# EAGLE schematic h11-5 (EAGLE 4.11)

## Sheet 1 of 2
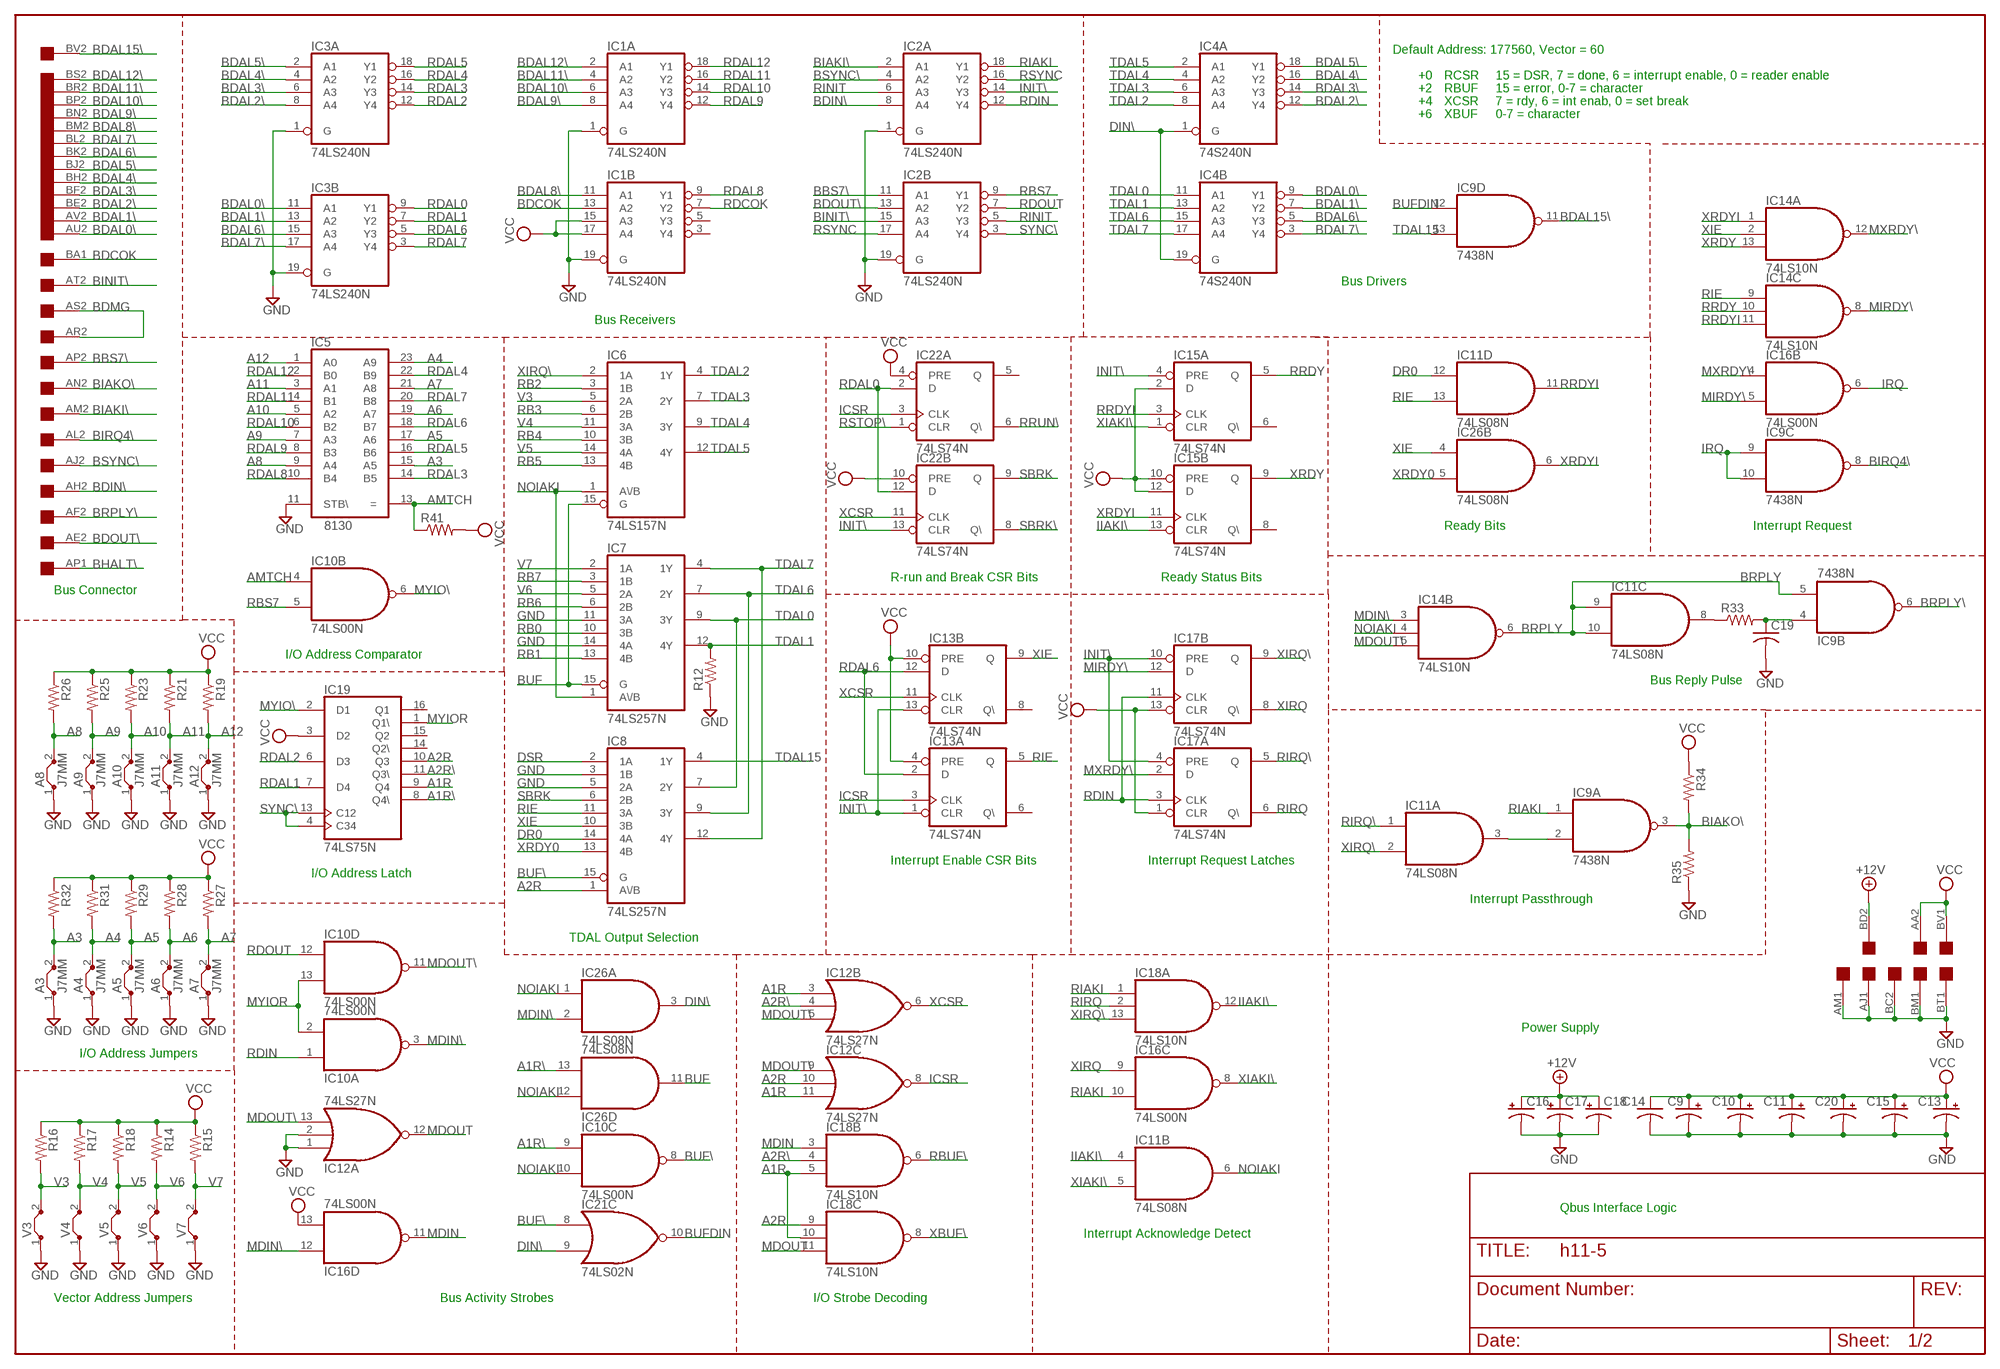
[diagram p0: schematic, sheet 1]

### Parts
A3  J7MM  [07]
A4  J7MM  [07]
A5  J7MM  [07]
A6  J7MM  [07]
A7  J7MM  [07]
A8  J7MM  [07]
A9  J7MM  [07]
A10  J7MM  [07]
A11  J7MM  [07]
A12  J7MM  [07]
C9  CPOL-USB45181B  [B45181B]
C10  CPOL-USB45181B  [B45181B]
C11  CPOL-USB45181B  [B45181B]
C13  CPOL-USB45181B  [B45181B]
C14  C-US075-032X103  [C075-032X103]
C15  CPOL-USB45181B  [B45181B]
C16  CPOL-USB45181B  [B45181B]
C17  CPOL-USB45181B  [B45181B]
C18  CPOL-USB45181B  [B45181B]
C19  C-US075-032X103  [C075-032X103]
C20  CPOL-USB45181B  [B45181B]
EDGE$  DOUBLE  [EDGE-CON4]
IC1  74LS240N  [DIL20]
IC2  74LS240N  [DIL20]
IC3  74LS240N  [DIL20]
IC4  74S240N  [DIL20]
IC5  8130  [DIL24]
IC6  74LS157N  [DIL16]
IC7  74LS257N  [DIL16]
IC8  74LS257N  [DIL16]
IC9  7438N  74LS38N  [DIL14]
IC10  74LS00N  [DIL14]
IC11  74LS08N  [DIL14]
IC12  74LS27N  [DIL14]
IC13  74LS74N  [DIL14]
IC14  74LS10N  [DIL14]
IC15  74LS74N  [DIL14]
IC16  74LS00N  [DIL14]
IC17  74LS74N  [DIL14]
IC18  74LS10N  [DIL14]
IC19  74LS75N  [DIL16]
IC21  74LS02N  [DIL14]
IC22  74LS74N  [DIL14]
IC26  74LS08N  [DIL14]
R12  R-US_0207/10  [0207/10]
R14  R-US_0207/10  [0207/10]
R15  R-US_0207/10  [0207/10]
R16  R-US_0207/10  [0207/10]
R17  R-US_0207/10  [0207/10]
R18  R-US_0207/10  [0207/10]
R19  R-US_0207/10  [0207/10]
R21  R-US_0207/10  [0207/10]
R23  R-US_0207/10  [0207/10]
R25  R-US_0207/10  [0207/10]
R26  R-US_0207/10  [0207/10]
R27  R-US_0207/10  [0207/10]
R28  R-US_0207/10  [0207/10]
R29  R-US_0207/10  [0207/10]
R31  R-US_0207/10  [0207/10]
R32  R-US_0207/10  [0207/10]
R33  R-US_0207/10  [0207/10]
R34  R-US_0207/10  [0207/10]
R35  R-US_0207/10  [0207/10]
R41  R-US_0207/10  [0207/10]
V3  J7MM  [07]
V4  J7MM  [07]
V5  J7MM  [07]
V6  J7MM  [07]
V7  J7MM  [07]

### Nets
+12V [Supply]: C16.+ C17.+ C18.+ EDGE$.BD2 ; also sheet 2
A1R: IC12.3(B:I0) IC12.11(C:I2) IC18.5(B:I2) IC18.10(C:I1) IC19.9(Q4)
A1R\: IC10.9(C:I0) IC19.8(Q4\) IC26.13(D:I1)
A2R: IC8.1(A\/B) IC12.10(C:I1) IC18.9(C:I0) IC19.10(Q3)
A2R\: IC12.4(B:I1) IC18.4(B:I1) IC19.11(Q3\)
A3: A3.2 IC5.15(A5) R32.2
A4: A4.2 IC5.23(A9) R31.2
A5: A5.2 IC5.17(A6) R29.2
A6: A6.2 IC5.19(A7) R28.2
A7: A7.2 IC5.21(A8) R27.2
A8: A8.2 IC5.9(A4) R26.2
A9: A9.2 IC5.7(A3) R25.2
A10: A10.2 IC5.5(A2) R23.2
A11: A11.2 IC5.3(A1) R21.2
A12: A12.2 IC5.1(A0) R19.2
AMTCH: IC5.13(=) IC10.4(B:I0) R41.1
BBS7\: EDGE$.AP2 IC2.11(B:A1)
BDAL0\: EDGE$.AU2 IC3.11(B:A1) IC4.9(B:Y1)
BDAL1\: EDGE$.AV2 IC3.13(B:A2) IC4.7(B:Y2)
BDAL2\: EDGE$.BE2 IC3.8(A:A4) IC4.12(A:Y4)
BDAL3\: EDGE$.BF2 IC3.6(A:A3) IC4.14(A:Y3)
BDAL4\: EDGE$.BH2 IC3.4(A:A2) IC4.16(A:Y2)
BDAL5\: EDGE$.BJ2 IC3.2(A:A1) IC4.18(A:Y1)
BDAL6\: EDGE$.BK2 IC3.15(B:A3) IC4.5(B:Y3)
BDAL7\: EDGE$.BL2 IC3.17(B:A4) IC4.3(B:Y4)
BDAL8\: EDGE$.BM2 IC1.11(B:A1)
BDAL9\: EDGE$.BN2 IC1.8(A:A4)
BDAL10\: EDGE$.BP2 IC1.6(A:A3)
BDAL11\: EDGE$.BR2 IC1.4(A:A2)
BDAL12\: EDGE$.BS2 IC1.2(A:A1)
BDAL15\: EDGE$.BV2 IC9.11(D:O)
BDCOK: EDGE$.BA1 IC1.13(B:A2)
BDIN\: EDGE$.AH2 IC2.8(A:A4)
BDMG: EDGE$.AR2 EDGE$.AS2
BDOUT\: EDGE$.AE2 IC2.13(B:A2)
BHALT\: EDGE$.AP1 ; also sheet 2
BIAKI\: EDGE$.AM2 IC2.2(A:A1)
BIAKO\: EDGE$.AN2 IC9.3(A:O) R34.2 R35.2
BINIT\: EDGE$.AT2 IC2.15(B:A3)
BIRQ4\: EDGE$.AL2 IC9.8(C:O)
BRPLY: IC9.5(B:I1) IC11.9(C:I0) IC11.10(C:I1) IC14.6(B:O)
BRPLY\: EDGE$.AF2 IC9.6(B:O)
BSYNC\: EDGE$.AJ2 IC2.4(A:A2)
BUF: IC6.15(G) IC7.15(G) IC26.11(D:O)
BUF\: IC8.15(G) IC10.8(C:O) IC21.8(C:I0)
BUFDIN: IC9.12(D:I0) IC21.10(C:O)
DIN\: IC4.1(A:G) IC4.19(B:G) IC21.9(C:I1) IC26.3(A:O)
DR0: IC8.14(4A) IC11.12(D:I0) ; also sheet 2
DSR: IC8.2(1A) ; also sheet 2
GND [Supply]: A3.1 A4.1 A5.1 A6.1 A7.1 A8.1 A9.1 A10.1 A11.1 A12.1 C9.- C10.- C11.- C13.- C14.2 C15.- C16.- C17.- C18.- C19.2 C20.- EDGE$.AJ1 EDGE$.AM1 EDGE$.BC2 EDGE$.BM1 EDGE$.BT1 IC1.1(A:G) IC1.19(B:G) IC2.1(A:G) IC2.19(B:G) IC3.1(A:G) IC3.19(B:G) IC5.11(STB\) IC7.11(3A) IC7.14(4A) IC8.3(1B) IC8.5(2A) IC12.1(A:I0) IC12.2(A:I1) R12.1 R35.1 V3.1 V4.1 V5.1 V6.1 V7.1 ; also sheet 2
ICSR: IC12.8(C:O) IC13.3(A:CLK) IC22.3(A:CLK)
IIAKI\: IC11.4(B:I0) IC15.13(B:CLR) IC18.12(A:O)
INIT\: IC2.14(A:Y3) IC13.1(A:CLR) IC13.13(B:CLR) IC15.4(A:PRE) IC17.4(A:PRE) IC17.10(B:PRE) IC22.13(B:CLR)
IRQ: IC9.9(C:I0) IC9.10(C:I1) IC16.6(B:O)
MDIN: IC16.11(D:O) IC18.3(B:I0)
MDIN\: IC10.3(A:O) IC14.3(B:I0) IC16.12(D:I0) IC26.2(A:I1)
MDOUT: IC12.12(A:O) IC18.11(C:I2)
MDOUT\: IC10.11(D:O) IC12.5(B:I2) IC12.9(C:I0) IC12.13(A:I2) IC14.5(B:I2)
MIRDY\: IC14.8(C:O) IC16.5(B:I1) IC17.12(B:D)
MXRDY\: IC14.12(A:O) IC16.4(B:I0) IC17.2(A:D)
MYIO\: IC10.6(B:O) IC19.2(D1)
MYIOR: IC10.2(A:I1) IC10.13(D:I1) IC19.1(Q1\)
N$7: IC9.2(A:I1) IC11.3(A:O)
N$12: IC11.8(C:O) R33.1
N$23: C19.1 IC9.4(B:I0) R33.2
NOIAKI: IC6.1(A\/B) IC7.1(A\/B) IC10.10(C:I1) IC11.6(B:O) IC14.4(B:I1) IC26.1(A:I0) IC26.12(D:I0)
RB0: IC7.10(3B) ; also sheet 2
RB1: IC7.13(4B) ; also sheet 2
RB2: IC6.3(1B) ; also sheet 2
RB3: IC6.6(2B) ; also sheet 2
RB4: IC6.10(3B) ; also sheet 2
RB5: IC6.13(4B) ; also sheet 2
RB6: IC7.6(2B) ; also sheet 2
RB7: IC7.3(1B) ; also sheet 2
RBS7: IC2.9(B:Y1) IC10.5(B:I1)
RBUF\: IC18.6(B:O) ; also sheet 2
RDAL0: IC3.9(B:Y1) IC22.2(A:D) IC22.12(B:D) ; also sheet 2
RDAL1: IC3.7(B:Y2) IC19.7(D4) ; also sheet 2
RDAL2: IC3.12(A:Y4) IC19.6(D3) ; also sheet 2
RDAL3: IC3.14(A:Y3) IC5.14(B5) ; also sheet 2
RDAL4: IC3.16(A:Y2) IC5.22(B9) ; also sheet 2
RDAL5: IC3.18(A:Y1) IC5.16(B6) ; also sheet 2
RDAL6: IC3.5(B:Y3) IC5.18(B7) IC13.2(A:D) IC13.12(B:D) ; also sheet 2
RDAL7: IC3.3(B:Y4) IC5.20(B8) ; also sheet 2
RDAL8: IC1.9(B:Y1) IC5.10(B4)
RDAL9: IC1.12(A:Y4) IC5.8(B3)
RDAL10: IC1.14(A:Y3) IC5.6(B2)
RDAL11: IC1.16(A:Y2) IC5.4(B1)
RDAL12: IC1.18(A:Y1) IC5.2(B0)
RDCOK: IC1.7(B:Y2) ; also sheet 2
RDIN: IC2.12(A:Y4) IC10.1(A:I0) IC17.3(A:CLK) IC17.11(B:CLK)
RDOUT: IC2.7(B:Y2) IC10.12(D:I0)
RIAKI: IC2.18(A:Y1) IC9.1(A:I0) IC16.10(C:I1) IC18.1(A:I0)
RIE: IC8.11(3A) IC11.13(D:I1) IC13.5(A:Q) IC14.9(C:I0)
RINIT: IC2.5(B:Y3) IC2.6(A:A3) ; also sheet 2
RIRQ: IC17.6(A:Q\) IC18.2(A:I1)
RIRQ\: IC11.1(A:I0) IC17.5(A:Q)
RRDY: IC14.10(C:I1) IC15.5(A:Q)
RRDYI: IC11.11(D:O) IC14.11(C:I2) IC15.3(A:CLK)
RRUN\: IC22.6(A:Q\) ; also sheet 2
RSTOP\: IC22.1(A:CLR) ; also sheet 2
RSYNC: IC2.16(A:Y2) IC2.17(B:A4)
SBRK: IC8.6(2B) IC22.9(B:Q)
SBRK\: IC22.8(B:Q\) ; also sheet 2
SYNC\: IC2.3(B:Y4) IC19.4(C34) IC19.13(C12)
TDAL0: IC4.11(B:A1) IC7.9(3Y) IC8.7(2Y)
TDAL1: IC4.13(B:A2) IC7.12(4Y) R12.2
TDAL2: IC4.8(A:A4) IC6.4(1Y)
TDAL3: IC4.6(A:A3) IC6.7(2Y)
TDAL4: IC4.4(A:A2) IC6.9(3Y)
TDAL5: IC4.2(A:A1) IC6.12(4Y)
TDAL6: IC4.15(B:A3) IC7.7(2Y) IC8.9(3Y)
TDAL7: IC4.17(B:A4) IC7.4(1Y) IC8.12(4Y)
TDAL15: IC8.4(1Y) IC9.13(D:I1)
V3: IC6.5(2A) R16.2 V3.2
V4: IC6.11(3A) R17.2 V4.2
V5: IC6.14(4A) R18.2 V5.2
V6: IC7.5(2A) R14.2 V6.2
V7: IC7.2(1A) R15.2 V7.2
VCC: C9.+ C10.+ C11.+ C13.+ C14.1 C15.+ C20.+ EDGE$.AA2 EDGE$.BV1 IC1.15(B:A3) IC1.17(B:A4) IC13.4(A:PRE) IC13.10(B:PRE) IC15.2(A:D) IC15.10(B:PRE) IC15.12(B:D) IC16.13(D:I1) IC17.1(A:CLR) IC17.13(B:CLR) IC19.3(D2) IC22.4(A:PRE) IC22.10(B:PRE) R14.1 R15.1 R16.1 R17.1 R18.1 R19.1 R21.1 R23.1 R25.1 R26.1 R27.1 R28.1 R29.1 R31.1 R32.1 R34.1 R41.2 ; also sheet 2
XBUF\: IC18.8(C:O) ; also sheet 2
XCSR: IC12.6(B:O) IC13.11(B:CLK) IC22.11(B:CLK)
XIAKI\: IC11.5(B:I1) IC15.1(A:CLR) IC16.8(C:O)
XIE: IC8.10(3B) IC13.9(B:Q) IC14.2(A:I1) IC26.4(B:I0)
XIRQ: IC16.9(C:I0) IC17.8(B:Q\)
XIRQ\: IC6.2(1A) IC11.2(A:I1) IC17.9(B:Q) IC18.13(A:I2)
XRDY: IC14.13(A:I2) IC15.9(B:Q)
XRDY0: IC8.13(4B) IC26.5(B:I1) ; also sheet 2
XRDYI: IC14.1(A:I0) IC15.11(B:CLK) IC26.6(B:O)
Unconnected: EDGE$.AA1 EDGE$.AB1 EDGE$.AB2 EDGE$.AC1 EDGE$.AC2 EDGE$.AD1 EDGE$.AD2 EDGE$.AE1 EDGE$.AF1 EDGE$.AH1 EDGE$.AK1 EDGE$.AK2 EDGE$.AL1 EDGE$.AN1 EDGE$.AR1 EDGE$.AS1 EDGE$.AT1 EDGE$.AU1 EDGE$.AV1 EDGE$.BA2 EDGE$.BB1 EDGE$.BB2 EDGE$.BC1 EDGE$.BD1 EDGE$.BE1 EDGE$.BF1 EDGE$.BH1 EDGE$.BJ1 EDGE$.BK1 EDGE$.BL1 EDGE$.BN1 EDGE$.BP1 EDGE$.BR1 EDGE$.BS1 EDGE$.BT2 EDGE$.BU1 EDGE$.BU2 IC1.3(B:Y4) IC1.5(B:Y3) IC13.6(A:Q\) IC13.8(B:Q\) IC15.6(A:Q\) IC15.8(B:Q\) IC19.14(Q2\) IC19.15(Q2) IC19.16(Q1) IC22.5(A:Q)

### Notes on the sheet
- Default Address: 177560, Vector = 60
- +0 | RCSR | 15 = DSR, 7 = done, 6 = interrupt enable, 0 = reader enable
- +2 | RBUF | 15 = error, 0-7 = character
- +4 | XCSR | 7 = rdy, 6 = int enab, 0 = set break
- +6 | XBUF | 0-7 = character
- Bus Drivers
- Bus Receivers
- Ready Bits | Interrupt Request
- R-run and Break CSR Bits | Ready Status Bits
- Bus Connector
- I/O Address Comparator
- Bus Reply Pulse
- Interrupt Enable CSR Bits | Interrupt Request Latches
- I/O Address Latch
- Interrupt Passthrough
- TDAL Output Selection
- Power Supply
- I/O Address Jumpers
- Qbus Interface Logic
- Interrupt Acknowledge Detect
- Vector Address Jumpers | Bus Activity Strobes | I/O Strobe Decoding

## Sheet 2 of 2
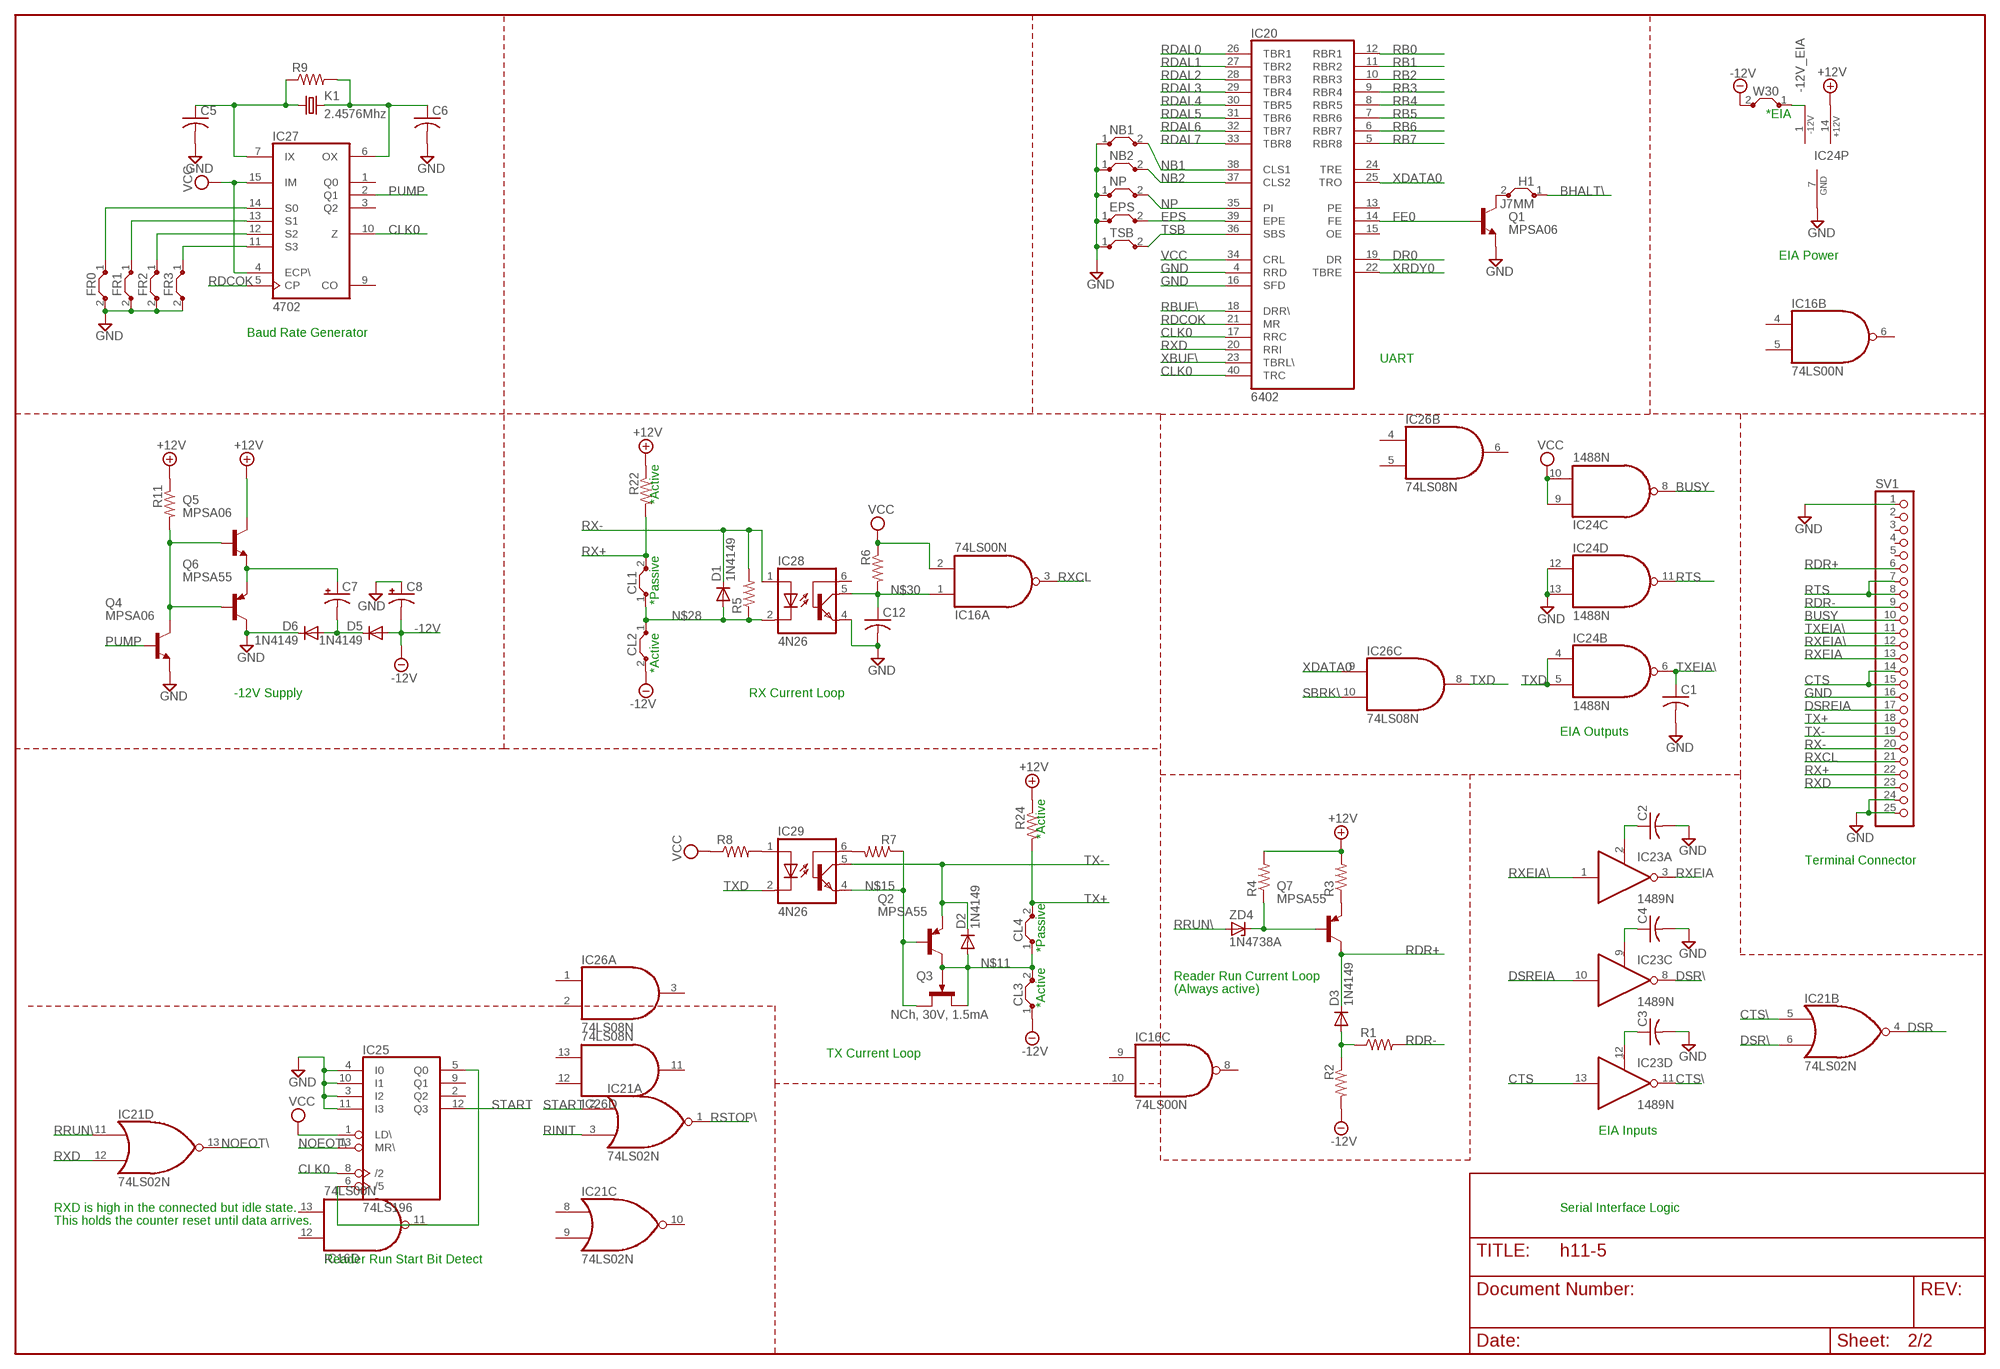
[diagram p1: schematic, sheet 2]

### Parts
C1  C-US075-032X103  [C075-032X103]
C2  C-US075-032X103  [C075-032X103]
C3  C-US075-032X103  [C075-032X103]
C4  C-US075-032X103  [C075-032X103]
C5  C-US075-032X103  [C075-032X103]
C6  C-US075-032X103  [C075-032X103]
C7  CPOL-USB45181B  [B45181B]
C8  CPOL-USB45181B  [B45181B]
C12  C-US075-032X103  [C075-032X103]
CL1  J7MM  [07]
CL2  J7MM  [07]
CL3  J7MM  [07]
CL4  J7MM  [07]
D1  1N4149  1N4148  [DO35-10]
D2  1N4149  1N4148  [DO35-10]
D3  1N4149  1N4148  [DO35-10]
D5  1N4149  1N4148  [DO35-10]
D6  1N4149  1N4148  [DO35-10]
EPS  J7MM  [07]
FR0  J7MM  [07]
FR1  J7MM  [07]
FR2  J7MM  [07]
FR3  J7MM  [07]
H1  J7MM  [07]
IC20  6402  HD6402  [DIL40]
IC23  1489N  [DIL14]
IC24  1488N  [DIL14]
IC25  74LS196  [DIL14]
IC27  4702  HD4702  [DIL16]
IC28  4N26  4N35  [DIL06]
IC29  4N26  4N35  [DIL06]
K1  2.4576Mhz  CRYTALHC33U-H  [HC33U-H]
NB1  J7MM  [07]
NB2  J7MM  [07]
NP  J7MM  [07]
Q1  MPSA06  -NPN-TO92L  [TO92L]
Q2  MPSA55  -PNP-TO92L  [TO92L]
Q3  NCh, 30V, 1.5mA  2N4391  [TO18E]
Q4  MPSA06  -NPN-TO92L  [TO92L]
Q5  MPSA06  -NPN-TO92L  [TO92L]
Q6  MPSA55  -PNP-TO92L  [TO92L]
Q7  MPSA55  -PNP-TO92L  [TO92L]
R1  R-US_0207/10  [0207/10]
R2  R-US_0207/10  [0207/10]
R3  R-US_0207/10  [0207/10]
R4  R-US_0207/10  [0207/10]
R5  R-US_0207/10  [0207/10]
R6  R-US_0207/10  [0207/10]
R7  R-US_0207/10  [0207/10]
R8  R-US_0207/10  [0207/10]
R9  R-US_0207/10  [0207/10]
R11  R-US_0411/12  [0411/12]
R22  R-US_0207/10  [0207/10]
R24  R-US_0207/10  [0207/10]
SV1  PINHD-1X25  [1X25]
TSB  J7MM  [07]
W30  J7MM  [07]
ZD4  1N4738A  1N4728  [DO41Z10]

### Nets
+12V [Supply]: IC24.14(P:+12V) Q5.3(C) R3.2 R4.2 R11.1 R22.1 R24.1 ; also sheet 1
-12V: C8.- CL2.2 CL3.1 D5.A R2.2 W30.2
-12V_EIA: IC24.1(P:-12V) W30.1
BHALT\: H1.1 ; also sheet 1
BUSY: IC24.8(C:O) SV1.10
CLK0: IC20.17(RRC) IC20.40(TRC) IC25.8(/2) IC27.10(Z)
CTS: IC23.13(D:I) SV1.14 SV1.15
CTS\: IC21.5(B:I0) IC23.11(D:O)
DR0: IC20.19(DR) ; also sheet 1
DSR: IC21.4(B:O) ; also sheet 1
DSR\: IC21.6(B:I1) IC23.8(C:O)
DSREIA: IC23.10(C:I) SV1.17
EPS: EPS.2 IC20.39(EPE)
FE0: IC20.14(FE) Q1.2(B)
GND [Supply]: C1.2 C2.2 C3.2 C4.2 C5.2 C6.2 C8.+ C12.2 D6.C EPS.1 FR0.2 FR1.2 FR2.2 FR3.2 IC20.4(RRD) IC20.16(SFD) IC24.7(P:GND) IC24.12(D:I0) IC24.13(D:I1) IC25.3(I2) IC25.4(I0) IC25.10(I1) IC25.11(I3) IC28.4(EMI) NB1.1 NB2.1 NP.1 Q1.1(E) Q4.1(E) Q6.3(C) SV1.1 SV1.16 SV1.24 SV1.25 TSB.1 ; also sheet 1
N$1: C2.1 IC23.2(A:RC)
N$2: FR0.1 IC27.14(S0)
N$3: H1.2 Q1.3(C)
N$4: FR1.1 IC27.13(S1)
N$5: FR2.1 IC27.12(S2)
N$6: FR3.1 IC27.11(S3)
N$9: C5.1 IC27.7(IX) K1.1 R9.1
N$10: C6.1 IC27.6(OX) K1.2 R9.2
N$11: CL3.2 CL4.1 D2.A Q2.3(C) Q3.D Q3.G
N$13: IC29.6(BAS) R7.2
N$15: IC29.4(EMI) Q2.2(B) Q3.S R7.1
N$16: IC29.1(A) R8.2
N$19: C4.1 IC23.9(C:RC)
N$20: C7.- D5.C D6.A
N$22: C7.+ Q5.1(E) Q6.1(E)
N$25: C3.1 IC23.12(D:RC)
N$26: Q4.3(C) Q5.2(B) Q6.2(B) R11.2
N$27: D3.A R1.1 R2.1
N$28: CL1.1 CL2.1 D1.A IC28.2(C) R5.1
N$29: Q7.2(B) R4.1 ZD4.C
N$30: C12.1 IC16.1(A:I0) IC28.5(COL) R6.2
N$31: Q7.1(E) R3.1
N$32: IC25.5(Q0) IC25.6(/5)
NB1: IC20.38(CLS1) NB1.2
NB2: IC20.37(CLS2) NB2.2
NOEOT\: IC21.13(D:O) IC25.13(MR\)
NP: IC20.35(PI) NP.2
PUMP: IC27.2(Q1) Q4.2(B)
RB0: IC20.12(RBR1) ; also sheet 1
RB1: IC20.11(RBR2) ; also sheet 1
RB2: IC20.10(RBR3) ; also sheet 1
RB3: IC20.9(RBR4) ; also sheet 1
RB4: IC20.8(RBR5) ; also sheet 1
RB5: IC20.7(RBR6) ; also sheet 1
RB6: IC20.6(RBR7) ; also sheet 1
RB7: IC20.5(RBR8) ; also sheet 1
RBUF\: IC20.18(DRR\) ; also sheet 1
RDAL0: IC20.26(TBR1) ; also sheet 1
RDAL1: IC20.27(TBR2) ; also sheet 1
RDAL2: IC20.28(TBR3) ; also sheet 1
RDAL3: IC20.29(TBR4) ; also sheet 1
RDAL4: IC20.30(TBR5) ; also sheet 1
RDAL5: IC20.31(TBR6) ; also sheet 1
RDAL6: IC20.32(TBR7) ; also sheet 1
RDAL7: IC20.33(TBR8) ; also sheet 1
RDCOK: IC20.21(MR) IC27.5(CP) ; also sheet 1
RDR+: D3.C Q7.3(C) SV1.6
RDR-: R1.2 SV1.9
RINIT: IC21.3(A:I1) ; also sheet 1
RRUN\: IC21.11(D:I0) ZD4.A ; also sheet 1
RSTOP\: IC21.1(A:O) ; also sheet 1
RTS: IC24.11(D:O) SV1.7 SV1.8
RX+: CL1.2 R22.2 SV1.22
RX-: D1.C IC28.1(A) R5.2 SV1.20
RXCL: IC16.3(A:O) SV1.21
RXD: IC20.20(RRI) IC21.12(D:I1) SV1.23
RXEIA: IC23.3(A:O) SV1.13
RXEIA\: IC23.1(A:I) SV1.12
SBRK\: IC26.10(C:I1) ; also sheet 1
START: IC21.2(A:I0) IC25.12(Q3)
TSB: IC20.36(SBS) TSB.2
TX+: CL4.2 R24.2 SV1.18
TX-: D2.C IC29.5(COL) Q2.1(E) SV1.19
TXD: IC24.4(B:I0) IC24.5(B:I1) IC26.8(C:O) IC29.2(C)
TXEIA\: C1.1 IC24.6(B:O) SV1.11
VCC: IC16.2(A:I1) IC20.34(CRL) IC24.9(C:I0) IC24.10(C:I1) IC25.1(LD\) IC27.4(ECP\) IC27.15(IM) R6.1 R8.1 ; also sheet 1
XBUF\: IC20.23(TBRL\) ; also sheet 1
XDATA0: IC20.25(TRO) IC26.9(C:I0)
XRDY0: IC20.22(TBRE) ; also sheet 1
Unconnected: IC20.13(PE) IC20.15(OE) IC20.24(TRE) IC23.4(B:I) IC23.5(B:RC) IC23.6(B:O) IC24.2(A:I) IC24.3(A:O) IC25.2(Q2) IC25.9(Q1) IC27.1(Q0) IC27.3(Q2) IC27.9(CO) IC28.6(BAS) SV1.2 SV1.3 SV1.4 SV1.5

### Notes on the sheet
- *EIA
- EIA Power
- Baud Rate Generator
- UART
- *Active
- *Passive
- *Active
- -12V Supply | RX Current Loop
- EIA Outputs
- *Active
- Terminal Connector
- *Passive
- *Active
- Reader Run Current Loop
- (Always active)
- TX Current Loop
- EIA Inputs
- RXD is high in the connected but idle state. | Serial Interface Logic
- This holds the counter reset until data arrives.
- Reader Run Start Bit Detect

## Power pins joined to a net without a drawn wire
GND: IC1.10(P:GND) IC2.10(P:GND) IC3.10(P:GND) IC4.10(P:GND) IC5.12(GND) IC6.8(GND) IC7.8(GND) IC8.8(GND) IC9.7(P:GND) IC10.7(P:GND) IC11.7(P:GND) IC12.7(P:GND) IC13.7(P:GND) IC14.7(P:GND) IC15.7(P:GND) IC16.7(P:GND) IC17.7(P:GND) IC18.7(P:GND) IC19.12(GND) IC20.3(GND) IC21.7(P:GND) IC22.7(P:GND) IC23.7(P:GND) IC25.7(GND) IC26.7(P:GND) IC27.8(GND)
VCC: IC1.20(P:VCC) IC2.20(P:VCC) IC3.20(P:VCC) IC4.20(P:VCC) IC5.24(VCC) IC6.16(VCC) IC7.16(VCC) IC8.16(VCC) IC9.14(P:VCC) IC10.14(P:VCC) IC11.14(P:VCC) IC12.14(P:VCC) IC13.14(P:VCC) IC14.14(P:VCC) IC15.14(P:VCC) IC16.14(P:VCC) IC17.14(P:VCC) IC18.14(P:VCC) IC19.5(VCC) IC20.1(VCC) IC21.14(P:VCC) IC22.14(P:VCC) IC23.14(P:VCC) IC25.14(VCC) IC26.14(P:VCC) IC27.16(VCC)

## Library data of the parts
A3-A12 CL1-CL4 EPS FR0 FR1-FR3 H1 NB1 NB2 NP TSB V3-V7 W30 = jumper:J: Bridge
C1-C6 C12 C14 C19 = rcl:C-US: CAPACITOR, American symbol
C7-C11 C13 C15-C18 C20 = rcl:CPOL-US: POLARIZED CAPACITOR, American symbol
D1-D3 D5 D6 = diode:1N4148: DIODE
EDGE$ = dec-con:DOUBLE: Double-Height DEC board
IC1-IC4 = 74xx-jameco:74*240: Octal BUFFER and LINE DRIVER, 3-state
IC5 = dec-con:8130: 10 bit comparator
IC6 = 74xx-jameco:74*157: Quadruple 2-line to 1-line data SELECTOR/MULTIPLEXER
IC7 IC8 = 74xx-jameco:74*257: Quadruple 2-to 1 line data SELECTOR/MULTIPLEXER
IC9 = 74xx-jameco:74*38: Quad 2-input NAND gate, open collector output
IC10 IC16 = 74xx-jameco:74*00: Quad 2-input NAND gate
IC11 IC26 = 74xx-jameco:74*08: Quad 2-input AND gate
IC12 = 74xx-jameco:74*27: Triple 3-input NOR gate
IC13 IC15 IC17 IC22 = 74xx-jameco:74*74: Dual D type positive edge triggered FLIP FLOP, preset and clear
IC14 IC18 = 74xx-jameco:74*10: Triple 3-input NAND gate
IC19 = 74xx-jameco:74*75: 4-bit bistable LATCH
IC20 = micro-harris:HD6402: MICROCONTROLLER/MEMORY DEVICE
IC21 = 74xx-jameco:74*02: Quad 2-input NOR gate
IC23 = interface:14*89: Quad line receivers BUFFER,
IC24 = interface:14*88: Quad 2-input NAND gate
IC25 = dec-con:74LS196: Loadable decade counter
IC27 = micro-harris:HD4702: MICROCONTROLLER/MEMORY DEVICE
IC28 IC29 = optocoupler:4N35: MOTOROLA OPTO COUPLER
K1 = crystal:CRYTAL: CRYSTAL
Q1 Q4 Q5 = transistor:*-NPN-: NPN Transistror
Q2 Q6 Q7 = transistor:*-PNP-: PNP Transistror
Q3 = transistor-small-signal:2N4391: N-CHANNEL FET
R1-R9 R11 R12 R14-R19 R21-R29 R31-R35 R41 = rcl:R-US_: RESISTOR, American symbol
SV1 = pinhead:PINHD-1X25: PIN HEADER
ZD4 = diode:1N4728: Z DIODE

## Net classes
1 Supply: width 0.635 mm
